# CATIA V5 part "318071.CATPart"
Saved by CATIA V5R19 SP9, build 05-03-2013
Part number: 318071
Source: Unknown
Bounding box of the stored display mesh (mm): x -147.762 to 15, y 107.861 to 128.446, z 477.184 to 504.918
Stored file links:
  D:\16-SIL\kale oto\R19_V2\318071.CATPart
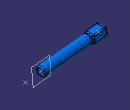
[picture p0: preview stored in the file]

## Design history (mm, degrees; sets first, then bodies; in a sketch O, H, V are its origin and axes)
Set1
  Point1 to Point3: stored without definition
  Plane1: stored without definition
Body1 "241\\236\\234\\MANIFOLD_SOLID_BREP #161559" (main body)
  Solid1: solid without history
